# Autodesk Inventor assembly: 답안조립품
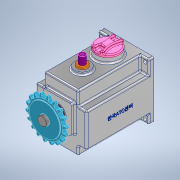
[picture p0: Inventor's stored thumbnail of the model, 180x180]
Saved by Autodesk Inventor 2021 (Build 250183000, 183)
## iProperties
Created: 2022-08
Part Number: 답안조립품
Document SubType Name: Assembly
Designer: Owner
Author: Owner
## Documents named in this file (16)
- C:\Users\Owner\Desktop\720810V1012\답안조립품.iam
- C:\Users\Owner\Desktop\720810V1012\본체.ipt
- C:\Users\Owner\Desktop\720810V1012\멈춤나사 M3.ipt
- C:\Users\Owner\Desktop\720810V1012\메인 축.ipt
- C:\Users\Owner\Desktop\720810V1012\베어링 608.ipt
- C:\Users\Owner\Desktop\720810V1012\베어링 6003.ipt
- C:\Users\Owner\Desktop\720810V1012\볼트 M4 x 10.ipt
- C:\Users\Owner\Desktop\720810V1012\부시.ipt
- C:\Users\Owner\Desktop\720810V1012\상부 캡.ipt
- C:\Users\Owner\Desktop\720810V1012\서브 축.ipt
- C:\Users\Owner\Desktop\720810V1012\스프로킷.ipt
- C:\Users\Owner\Desktop\720810V1012\슬라이더.ipt
- C:\Users\Owner\Desktop\720810V1012\오일 실 8 x 22 x 7.ipt
- C:\Users\Owner\Desktop\720810V1012\오일 실 17 x 32 x 8.ipt
- C:\Users\Owner\Desktop\720810V1012\커버.ipt
- C:\Users\Owner\Desktop\720810V1012\키 5 x 5.ipt
